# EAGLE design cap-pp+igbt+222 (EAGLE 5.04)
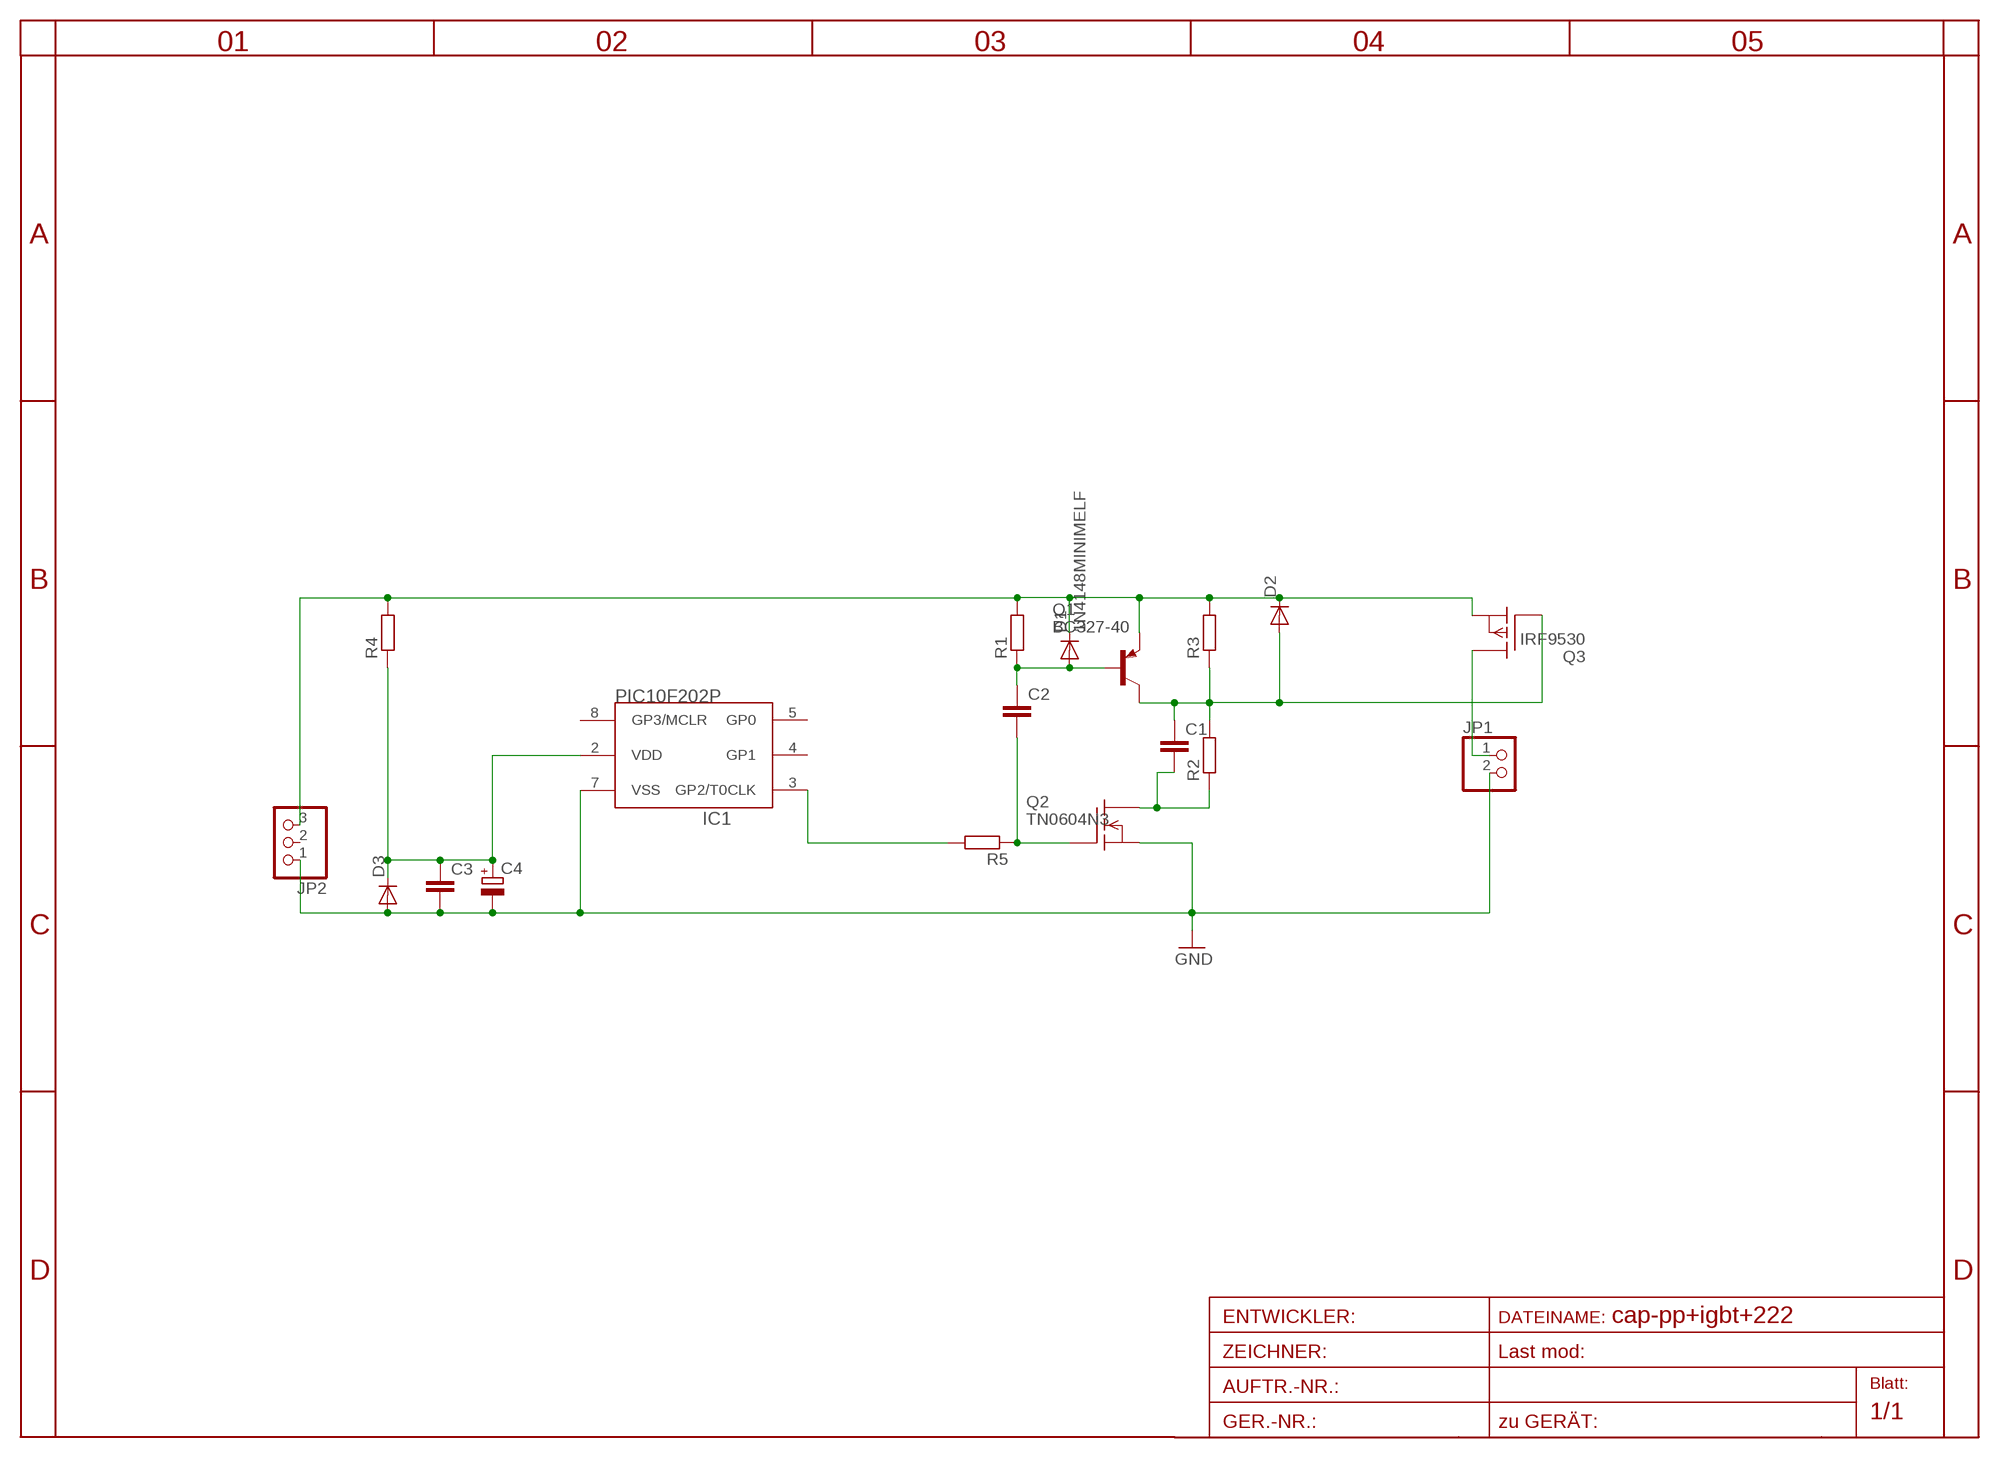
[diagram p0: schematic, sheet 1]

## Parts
C1  C-EU025_050-025X075  [C025_050-025X075]
C2  C-EU025_050-025X075  [C025_050-025X075]
C3  C-EU025_050-025X075  [C025_050-025X075]
C4  CPOL-EU5-13  [2,5-5-FLAT]
D1  1N4148MINIMELF  [MINIMELF]
D2  DIODE-D-5  [D-5]
D3  DIODE-D-5  [D-5]
IC1  PIC10F202P  [DIL8]
JP1  PINHD-1X2  [1X02]
JP2  PINHD-1X3  [1X03]
Q1  BC327-40  [TO92-EBC]
Q2  TN0604N3  [TO-92]
Q3  IRF9530  [TO220]
R1  R-EU_0204/2V  [0204V]
R2  R-EU_0204/2V  [0204V]
R3  R-EU_0204/2V  [0204V]
R4  R-EU_0204/2V  [0204V]
R5  R-EU_0204/2V  [0204V]

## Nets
BB: C2.2 Q2.2(G) R5.1
DRAIN: JP1.1 Q3.2(D)
GND: C3.2 C4.- D3.A IC1.7(VSS) JP1.2 JP2.1 Q2.1(S)
N$1: C1.2 Q2.3(D) R2.1
N$3: IC1.3(GP2/T0CLK) R5.2
N$4: C3.1 C4.+ D3.C IC1.2(VDD) R4.1
OUT: C1.1 D2.A Q1.C Q3.1(G) R2.2 R3.1
TB: C2.1 D1.A Q1.B R1.1
V+: D1.C D2.C JP2.3 Q1.E Q3.3(S) R1.2 R3.2 R4.2
Unconnected: IC1.4(GP1) IC1.5(GP0) IC1.8(GP3/MCLR) JP2.2

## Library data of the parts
C1-C3 = rcl-2:C-EU: CAPACITOR, European symbol
C4 = rcl-2:CPOL-EU: POLARIZED CAPACITOR, European symbol
D1 = diode-1:1N4148: DIODE
D2 D3 = diode-1:DIODE-: DIODE
IC1 = microchip-5:PIC10F20*: uPC nW 0,25/0,5k Program Flash memory
JP1 = pinhead:PINHD-1X2: PIN HEADER
JP2 = pinhead:PINHD-1X3: PIN HEADER
Q1 = transistor-pnp:BC327*: PNP Transistror
Q2 = transistor-fet:TN0604N3: N-Channel Enhancement MOSFET 40V; 4A; 0,75Ohm
Q3 = transistor-fet:IRF9530: P-Channel Enhancement MOSFET (HEXFET); -100V; -12A; 0,3Ohm
R1-R5 = rcl-2:R-EU_: RESISTOR, European symbol

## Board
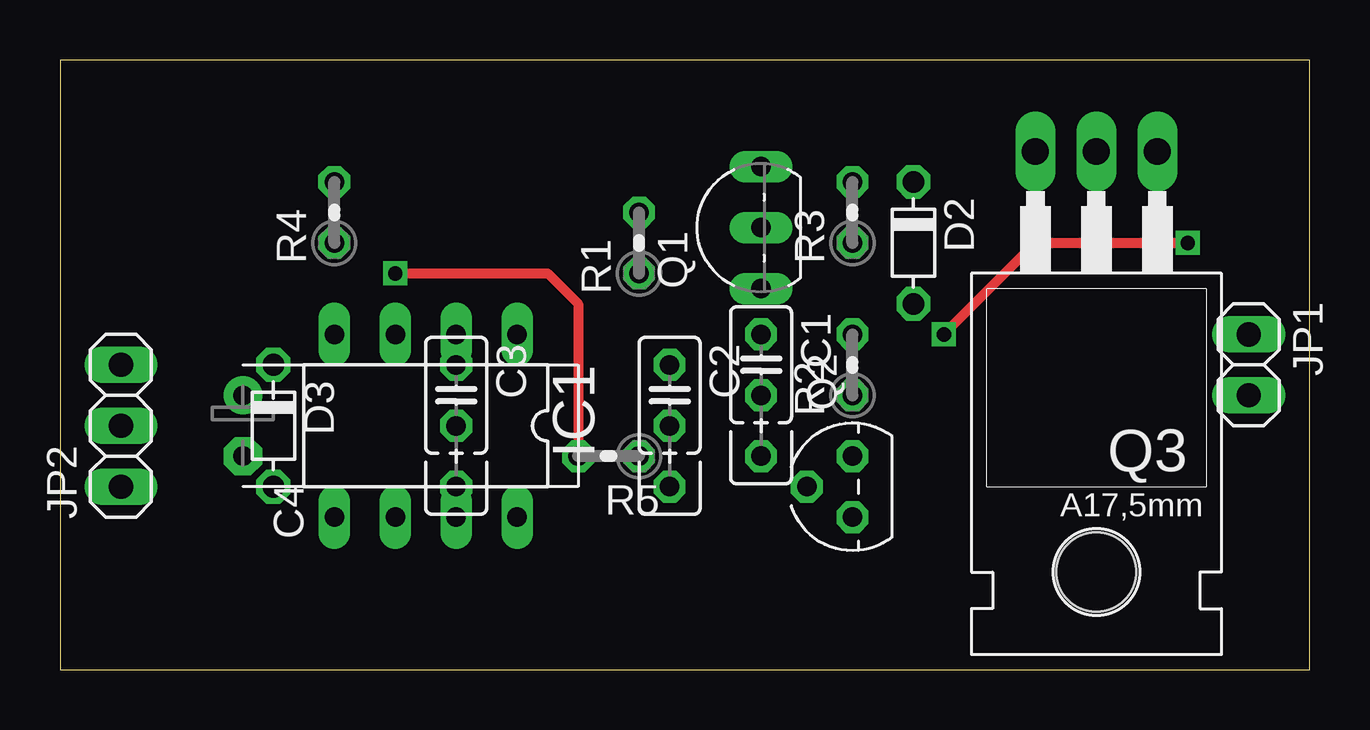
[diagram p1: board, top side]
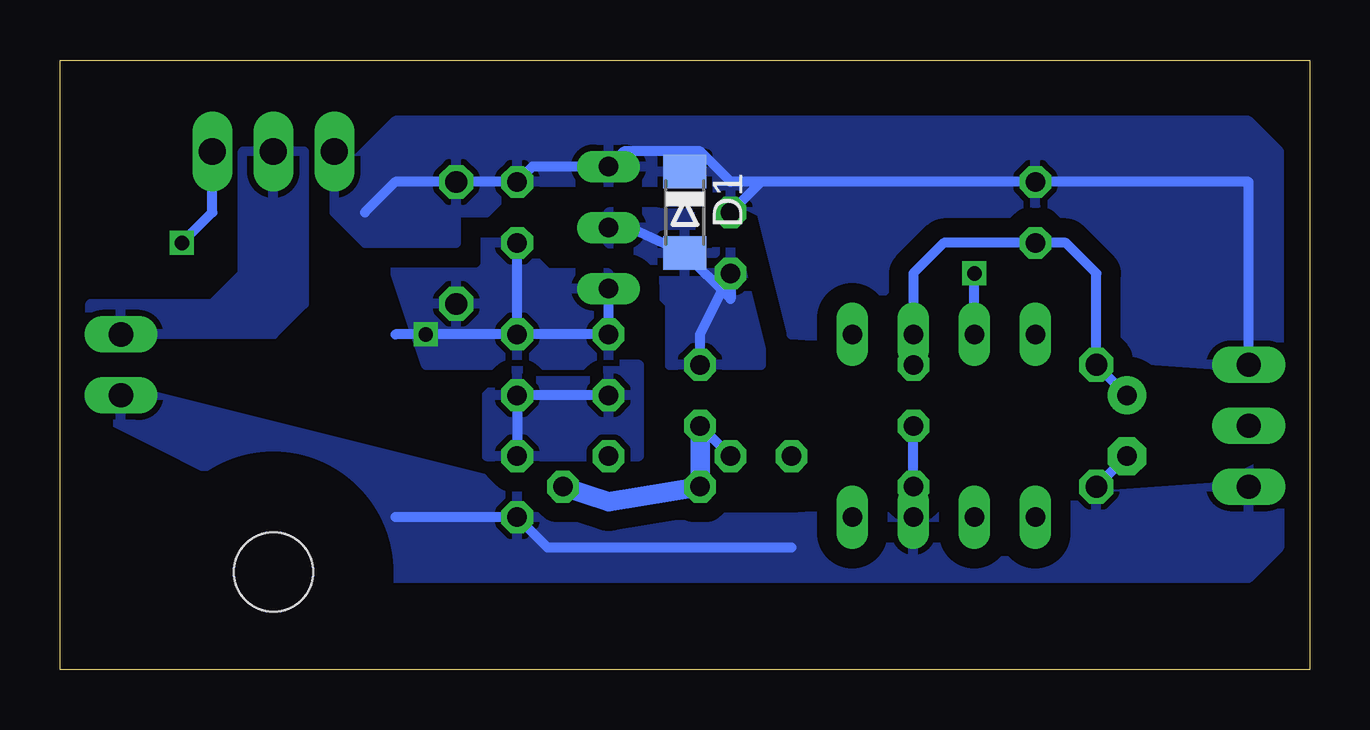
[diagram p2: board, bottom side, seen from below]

Size 52.07 x 25.4 mm. Coordinates in mm from the lower left corner, seen from the top.
Outline: 0,0 52.07,0 52.07,25.4 0,25.4 0,0
Copper layers (1*16): Top 0.035mm / dielectric 1.5mm / Bottom 0.035mm
Design rules "default": minimum track width 10mil, minimum drill 24mil, track to track 8mil, track to pad 8mil, pad to pad 8mil, via to via 8mil, smd to smd 8mil, copper to edge 40mil, drill to drill 8mil, minimum pad ring 10mil, minimum via ring 8mil, stop-mask expansion 4mil, vias tented up to drill 0mil, thermal gap 10mil

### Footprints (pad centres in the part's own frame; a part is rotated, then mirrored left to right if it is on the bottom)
C025_050-025X075 = drill 0.813 octagon: 1 -1.27,0; 2 1.27,0; 3 3.81,0
2,5-5-FLAT = drill 0.813 pad 1.6 round: + -1.27,0 | drill 0.813 pad 1.6 octagon: - 1.27,0
MINIMELF = smd 1.4 x 1.8: A 1.7,0; C -1.7,0
D-5 = drill 0.9 octagon: A 2.54,0; C -2.54,0
DIL8 = drill 0.813 long: 1 -3.81,-3.81; 2 -1.27,-3.81; 3 1.27,-3.81; 4 3.81,-3.81; 5 3.81,3.81; 6 1.27,3.81; 7 -1.27,3.81; 8 -3.81,3.81
1X02 = drill 1.016 long: 1 -1.27,0; 2 1.27,0
1X03 = drill 1.016 long: 1 -2.54,0; 2 0,0; 3 2.54,0
TO92-EBC = drill 0.813 long: B 0,-1.27; C -2.54,-1.27; E 2.54,-1.27
TO-92 = drill 0.813 octagon: 1 -1.27,0; 2 0,1.905; 3 1.27,0
TO220 = drill 1.118 long: 1 -2.54,-6.35; 2 0,-6.35; 3 2.54,-6.35 | hole 3.302: 0,11.176
0204V = drill 0.813 octagon: 1 -1.27,0; 2 1.27,0

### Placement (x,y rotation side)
C1  29.21,12.7 270 top
C2  25.4,11.43 270 top
C3  16.51,11.43 270 top
C4  7.62,10.16 270 top
D1  26.04,19.05 270 bottom
D2  35.56,17.78 270 top
D3  8.89,10.16 270 top
IC1  15.24,10.16 180 top
JP1  49.53,12.7 270 top
JP2  2.54,10.16 90 top
Q1  27.94,18.41 90 top
Q2  33.02,7.62 90 top
Q3  43.18,15.24 180 top
R1  24.13,17.78 90 top
R2  33.02,12.7 90 top
R3  33.02,19.05 90 top
R4  11.43,19.05 90 top
R5  22.86,8.89 180 top

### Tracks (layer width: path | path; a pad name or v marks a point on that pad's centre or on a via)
BB
  Bottom 0.406: R5.1 C2.2
  Bottom 0.813: Q2.2 29.21,6.99 25.4,7.62 C2.2
DRAIN
  pour Bottom: 41.91,21.59 41.91,15.24 43.18,13.97 50.8,13.97 50.8,15.24 45.72,15.24 44.45,16.51 44.45,21.59
GND
  Bottom 0.406: 21.59,5.08 31.75,5.08 Q2.1 38.1,6.35 | C4.- D3.A | IC1.7 C3.2
  pour Bottom (isolate 0.813): 1.27,8.89 1.27,5.08 2.54,3.81 39.37,3.81 41.91,6.35 52.07,11.43 48.26,11.43 33.02,7.62 31.75,6.35 21.59,6.35 3.81,7.62
N$1
  Bottom 0.406: C1.2 R2.1 Q2.3
  pour Bottom (isolate 0.254, rank 3): 27.94,12.7 33.02,12.7 34.29,11.43 34.29,8.89 27.94,8.89
N$3  (via drill 0.6)
  Top 0.406: v13.97,16.51 20.32,16.51 21.59,15.24 R5.2
  Bottom 0.406: IC1.3 v13.97,16.51
N$4
  Bottom 0.406: C4.+ D3.C 8.89,16.51 10.16,17.78 R4.1 15.24,17.78 16.51,16.51 IC1.2 C3.1
OUT  (via drill 0.6)
  Top 0.406: v46.99,17.78 40.64,17.78 v36.83,13.97
  Bottom 0.406: R2.2 v36.83,13.97 38.1,13.97 | R2.2 C1.1 Q1.C | R2.2 R3.1 | Q3.1 45.72,19.05 v46.99,17.78
  pour Bottom (isolate 0.813, rank 2): 29.21,16.51 31.75,16.51 33.02,17.78 38.1,17.78 38.1,16.51 36.83,12.7 29.21,12.7
TB
  Bottom 0.406: C2.1 25.4,13.97 R1.1 24.13,15.45 D1.A 28.78,18.62 29,18.62 Q1.B
  pour Bottom (isolate 0.813, rank 3): 26.67,12.7 22.86,12.7 22.86,16.51 25.4,19.05 29.21,19.05 29.21,17.78 26.67,15.24
V+
  Bottom 0.406: JP2.3 2.54,20.32 22.86,20.32 | 22.86,20.32 24.13,20.32 25.4,21.59 26.67,21.59 | 26.67,21.59 28.57,21.59 Q1.E 32.38,20.95 R3.2 38.1,20.32 39.37,19.05 | D1.C 26.04,20.95 26.67,21.59 | 22.86,20.32 R1.2
  pour Bottom (isolate 0.813): 1.27,12.7 1.27,21.59 2.54,22.86 38.1,22.86 40.64,20.32 40.64,19.05 39.37,17.78 35.56,17.78 35.56,19.05 34.29,19.05 33.02,20.32 25.4,20.32 22.86,19.05 21.59,13.97 3.81,12.7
